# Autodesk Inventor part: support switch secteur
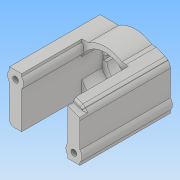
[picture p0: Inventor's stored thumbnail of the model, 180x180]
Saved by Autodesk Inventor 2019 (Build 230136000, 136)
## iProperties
Created: 2024-08
Part Number: support switch secteur
Material: Générique
Document SubType Name: Modeling
Designer: admin
Density: 1 g/cm^3
Appearance: Par défaut
Author: admin
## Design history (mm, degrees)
sketch "Esquisse1"
  geometry: L1 (-17.5, 12.5)-(17.5, 12.5); L2 (17.5, 12.5)-(17.5, -12.5); L3 (17.5, -12.5)-(-17.5, -12.5); L4 (-17.5, -12.5)-(-17.5, 12.5); 1 further point
  constraints: 8 end point, 2 parallel, 1 horizontal, 1 perpendicular
  dimensions: "d1" = 35 distance of L1.start L1.end; "d2" = 17.5 distance from line of point (0, 0) L4 (= 0.5 x d1); "d4" = 25 distance of L3.end L1.start; "d5" = 12.5 distance from line of point (0, 0) L1 (= 0.5 x d4)
extrude "Extrusion1" new body sketch "Esquisse1" distance "d6" = 5; taper "d7" = 0 deg
sketch "Esquisse2"
  geometry: L1 (-17.5, 12.5)-(-17.5, -12.5) reference; L2 (-17.5, 12.5)-(-11.5, 12.5); L3 (-11.5, 12.5)-(-11.5, -12.5); L4 (-11.5, -12.5)-(-17.5, -12.5); L5 (-17.5, -12.5)-(-17.5, 12.5); L6 (17.5, 12.5)-(-17.5, 12.5) reference; L7 (17.5, 12.5)-(11.5, 12.5); L8 (11.5, 12.5)-(11.5, -12.5); L9 (11.5, -12.5)-(17.5, -12.5); L10 (17.5, -12.5)-(17.5, 12.5); 1 further point
  constraints: 16 end point, 4 parallel, 2 horizontal, 2 perpendicular, 1 point on line
  dimensions: "d8" = 6 distance between parallel lines of L1 L3; "d9" = 6 distance between parallel lines of L10 L8
extrude "Extrusion2" join sketch "Esquisse2" distance "d10" = 40; taper "d11" = 0 deg
sketch "Esquisse3"
  geometry: L1 (10.75, -1.25)-(9.165, -1.25); L2 (9.165, 1.25)-(10.75, 1.25); L3 (10.75, 1.25)-(10.75, -1.25); L4 (2, -11.75)-(-2, -11.75); L5 (-2, 11.75)-(2, 11.75); L6 (2, 11.75)-(2, 9.031); L7 (2, -9.031)-(2, -11.75); L8 (-2, -11.75)-(-2, -9.031); L9 (-2, 9.031)-(-2, 11.75); A1 r 9.25 centre (0, 0) between (2, -9.031) and (9.165, -1.25); A2 r 9.25 centre (0, 0) between (9.165, 1.25) and (2, 9.031); A3 r 9.25 centre (0, 0) between (-2, 9.031) and (-2, -9.031); 1 further point
  constraints: 18 end point, 6 parallel, 6 point on circle, 3 centre point, 2 horizontal, 2 perpendicular, 1 coincident
  dimensions: "d13" = 2.5 distance of L2.end L1.start; "d14" = 1.25 vertical distance of L1.start point (0, 0) (= 0.5 x d13); "d16" = 4 distance of L5.start L5.end; "d18" = 11.75 distance from line of A1.centre L4; "d19" = 11.75 distance from line of point (0, 0) L5 (= d18)
extrude "Extrusion3" cut sketch "Esquisse3" distance "d20" = 40; taper "d21" = 0 deg
sketch "Esquisse4"
  geometry: L1 (10.75, 1.25)-(10.75, -1.25) reference; L2 (10.75, -1.25)-(9.165, -1.25) reference; L3 (2, -9.031)-(2, -11.75) reference; L4 (2, -11.75)-(-2, -11.75) reference; L5 (-2, -11.75)-(-2, -9.031) reference; L6 (-2, 9.031)-(-2, 11.75) reference; L7 (-2, 11.75)-(2, 11.75) reference; L8 (2, 11.75)-(2, 9.031) reference; L9 (9.165, 1.25)-(10.75, 1.25) reference; L10 (17.5, 12.5)-(-17.5, 12.5) reference; L11 (-17.5, 12.5)-(-17.5, -12.5) reference; L12 (-17.5, -12.5)-(17.5, -12.5) reference; L13 (17.5, -12.5)-(17.5, 12.5) reference; A1 r 9.25 centre (0, 0) between (2, -9.031) and (9.165, -1.25) reference; A2 r 9.25 centre (0, 0) between (-2, 9.031) and (-2, -9.031) reference; A3 r 9.25 centre (0, 0) between (9.165, 1.25) and (2, 9.031) reference; A4 r 15 centre (0, 0) between (8.292, 12.5) and (-8.292, 12.5); A5 r 15 centre (0, 0) between (-8.292, -12.5) and (8.292, -12.5); 1 further point
  constraints: 4 point on circle, 4 point on line, 2 centre point, 1 coincident
extrude "Extrusion4" join sketch "Esquisse4" stored distance "d23" = 40; taper "d24" = 0 deg
sketch "Esquisse5"
  geometry: L1 (-17.5, -12.5)-(-8.292, -12.5) reference; L2 (-17.5, 12.5)-(-17.5, -12.5) reference; L3 (17.5, 12.5)-(8.292, 12.5) reference; L4 (17.5, -12.5)-(17.5, 12.5) reference; C1 r 1.425 at (14.5, 8.5); C2 r 1.425 at (-14.5, -8.5); 1 further point
  constraints: 2 centre point
  dimensions: "d25" = 4 distance from line of L1 C2.centre; "d26" = 3 distance from line of L2 C2.centre; "d27" = 4 distance from line of L3 C1.centre; "d28" = 3 distance from line of L4 C1.centre; "d29" = 2.85 diameter of C1; "d30" = 2.85 diameter of C2
extrude "Extrusion5" cut sketch "Esquisse5" extent not by distance; stored distance "d31" = 40; taper "d32" = 0 deg
sketch "Esquisse6"
  geometry: C1 r 1.425 at (14.5, 8.5) reference; C2 r 1.425 at (-14.5, -8.5) reference; C3 r 2.4 at (14.5, 8.5); C4 r 2.4 at (-14.5, -8.5); 1 further point
  constraints: 2 centre point, 2 coincident
  dimensions: "d33" = 4.8 diameter of C3; "d34" = 4.8 diameter of C4
extrude "Extrusion6" cut sketch "Esquisse6" distance "d35" = 35; taper "d36" = 0 deg
sketch "Esquisse7"
  geometry: C1 r 2.4 at (14.5, 8.5) reference; C2 r 2.4 at (-14.5, -8.5) reference; C3 r 4 at (14.5, 8.5); C4 r 4 at (-14.5, -8.5); 1 further point
  constraints: 2 centre point, 2 coincident
  dimensions: "d37" = 8 diameter of C3; "d38" = 8 diameter of C4
extrude "Extrusion7" join sketch "Esquisse7" stored distance "d39" = 0; taper "d40" = 0 deg
fillet "Congé1" dims "d41" = 2
chamfer "Chanfrein1" distance "d42" = 4; stored, may be unused: second distance "d43" = 2, angle "d44" = 45 deg
sketch "Esquisse8"
  geometry: L1 (11.5, 12.5)-(11.5, -5.854) reference; L2 (11.5, 12.5)-(8.292, 12.5) reference; L3 (-8.292, 12.5)-(-11.5, 12.5) reference; L4 (-11.5, 11.146)-(-11.5, 12.5) reference; L5 (-11.5, -12.5)-(-8.292, -12.5) reference; L6 (8.292, -12.5)-(11.5, -12.5) reference; L7 (11.5, -11.146)-(11.5, -12.5) reference; L8 (11.5, -4.899)-(11.5, -12.5); L9 (11.5, -12.5)-(8.292, -12.5); L10 (-8.292, -12.5)-(-11.5, -12.5); L11 (-11.5, -12.5)-(-11.5, -4.899); L12 (-11.5, -12.5)-(-11.5, 5.854) reference; L13 (11.5, 4.899)-(11.5, 12.5); L14 (8.292, 12.5)-(13.5, 12.5) reference; L15 (11.5, 12.5)-(8.292, 12.5); L16 (-11.5, 4.899)-(-11.5, 12.5); L17 (-17.5, 12.5)-(-8.292, 12.5) reference; L18 (-11.5, 12.5)-(-8.292, 12.5); A1 r 15 centre (0, 0) between (8.292, 12.5) and (-8.292, 12.5) reference; A2 r 4 centre (-14.5, 8.5) between (-11.5, 5.854) and (-11.5, 11.146) reference; A3 r 15 centre (0, 0) between (-8.292, -12.5) and (8.292, -12.5) reference; A4 r 4 centre (14.5, -8.5) between (11.5, -5.854) and (11.5, -11.146) reference; A5 r 12.5 centre (0, 0) between (11.5, 4.899) and (-11.5, 4.899); A6 r 12.5 centre (0, 0) between (-11.5, -4.899) and (11.5, -4.899); A7 r 15 centre (0, 0) between (8.292, 12.5) and (-8.292, 12.5) reference; 1 further point
  constraints: 16 end point, 4 point on circle, 4 point on line, 3 perpendicular, 2 centre point, 2 collinear, 2 horizontal, 1 coincident, 1 vertical
extrude "Extrusion8" join sketch "Esquisse8" distance "d46" = 10; taper "d47" = 0 deg
chamfer "Chanfrein2" distance "d49" = 3; stored, may be unused: second distance "d50" = 2, angle "d51" = 45 deg
fillet "Congé3" dims "d52" = 4
sketch "Esquisse9"
  geometry: L1 (11.5, 12.086)-(14.886, 10.683) reference; L2 (11.5, 12.086)-(11.5, -5.854) reference; L3 (17.5, -5.854)-(17.5, 6.843) reference; L4 (11.5, 12.086)-(21.087, 12.086); L5 (21.087, 12.086)-(21.087, 8.086); L6 (21.087, 8.086)-(11.5, 8.086); L7 (11.5, 8.086)-(11.5, 12.086); 3 further points
  constraints: 8 end point, 2 parallel, 2 point on line, 1 horizontal, 1 perpendicular
  dimensions: "d56" = 4 distance between parallel lines of L4 L6
extrude "Extrusion9" cut sketch "Esquisse9" distance "d54" = 3; taper "d55" = 0 deg
sketch "Esquisse10"
  geometry: L1 (11.5, 12.086)-(14.886, 10.683) reference; L2 (11.5, 8.086)-(11.5, 12.086) reference; L3 (17.302, 8.086)-(11.5, 8.086) reference; L4 (16.184, 9.816)-(16.328, 9.672) reference; L5 (17.302, 8.086)-(11.5, 10.086); A1 r 4 centre (13.5, 6.843) between (17.302, 8.086) and (16.328, 9.672) reference; A2 r 4 centre (13.356, 6.988) between (16.184, 9.816) and (14.886, 10.683) reference; 1 further point
  constraints: 2 end point, 1 midpoint
  dimensions: "d57" = 2 distance from line of L3 L5.end (derived)
extrude "Extrusion10" join sketch "Esquisse10" distance "d58" = 3; taper "d59" = 0 deg
chamfer "Chanfrein3" distance "d60" = 1; stored, may be unused: second distance "d61" = 2, angle "d62" = 45 deg
node "Solide1"
node "Boucle projetée1"
node "Boucle projetée2"
other parameters: "d12" = 18.5, "d15" = 1.5, "d17" = 2 (= 0.5 x d16), "d45" = 25
